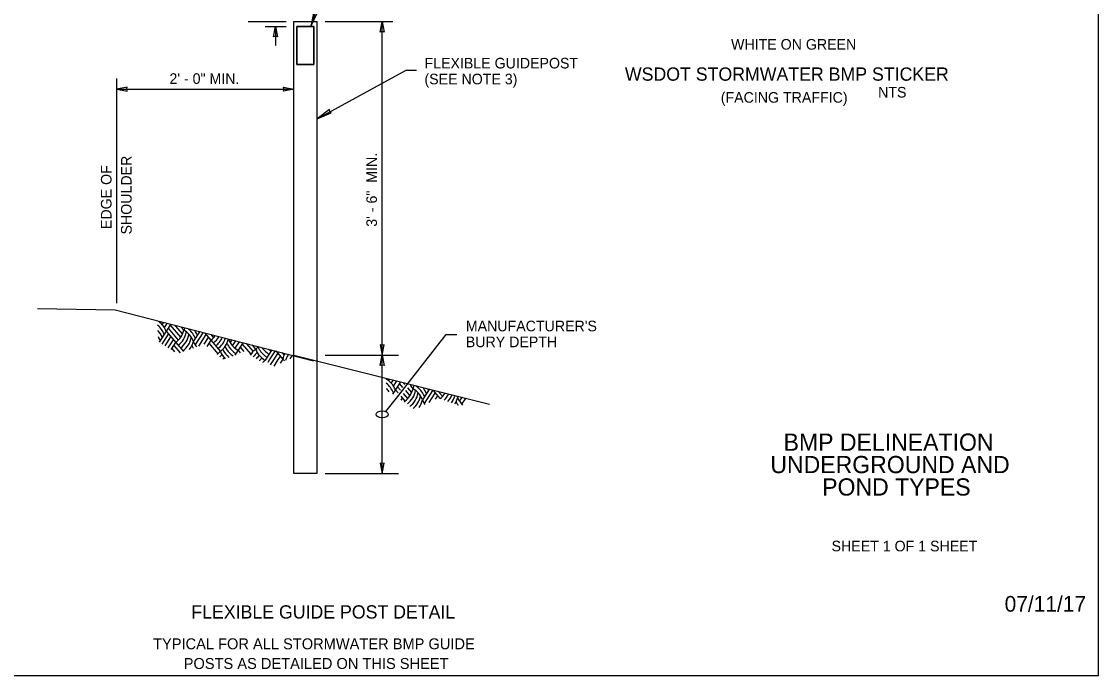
# Model space of a CAD drawing. Extents: x 99862 to 103151, y 100000 to 102076.
# Drawn here: x 101526 to 103151, y 100000 to 100986 of the extents above; entities that cross this region are included whole.
import ezdxf

# ---------------------------------------------------------------- set-up
doc = ezdxf.new("R2010")
doc.units = 0
for name, color, linetype in [('Default', 7, 'Continuous'), ('EV_EC_VegetativeFilterStripNew', 7, 'Continuous'), ('Level 1', 7, 'Continuous'), ('Level 13', 7, 'Continuous'), ('Level 15', 7, 'Continuous'), ('Level 20', 7, 'Continuous'), ('Level 4', 7, 'Continuous'), ('Level 5', 7, 'Continuous'), ('Level 62', 7, 'Continuous'), ('SH_DE_DetailLevel9', 7, 'Continuous')]:
    doc.layers.add(name, color=color, linetype=linetype)

msp = doc.modelspace()

# ---------------------------------------------------------------- linework, layer by layer
at = {"layer": 'Default'}
for p, q in [((101549.7, 100553.4), (101667.1, 100551.1)), ((101936.8, 100482.8), (102017, 100462.7)), ((102017, 100462.7), (102231.7, 100409.1))]:
    msp.add_line(p, q, dxfattribs=at)
at = {"layer": 'EV_EC_VegetativeFilterStripNew'}
msp.add_line((101667.1, 100551.1), (101966.1, 100474.4), dxfattribs=at)
at = {"layer": 'Level 1'}
msp.add_lwpolyline([(99862, 99999.5), (103151, 99999.5), (103151, 102075.5), (99862, 102075.5)], close=True, dxfattribs=at)
at = {"layer": 'Level 13'}
for p, q in [((101733.9, 100532.7), (101734.3, 100533.3)), ((101737.8, 100528.9), (101739.8, 100531.9)), ((101741.2, 100524.4), (101745.2, 100530.5)), ((101750.7, 100529.1), (101744, 100518.9)), ((101750, 100528.2), (101765.7, 100509.8)), ((101744, 100518.9), (101733.3, 100502.5)), ((101737.8, 100499.7), (101747.6, 100514.7)), ((101744, 100518.9), (101758.4, 100502)), ((101747, 100523.5), (101762.3, 100505.6)), ((101757.7, 100527.4), (101768.5, 100514.8)), ((101766.6, 100525.1), (101770.5, 100520.6)), ((101794.3, 100518.1), (101784.9, 100503.7)), ((101787.7, 100498.2), (101799.8, 100516.8)), ((101793, 100496.7), (101804.2, 100513.9)), ((101802.3, 100516.1), (101811.5, 100505.4)), ((101811.2, 100513.9), (101815.4, 100509)), ((101742.3, 100496.9), (101751.2, 100510.5)), ((101746.8, 100494.1), (101754.8, 100506.2)), ((101751.3, 100491.2), (101758.4, 100502)), ((101755.3, 100497.4), (101764.9, 100486.2)), ((101758.4, 100502), (101770.2, 100488.2)), ((101801.2, 100499.4), (101807.9, 100509.7)), ((101811.5, 100505.4), (101805.3, 100496.1)), ((101808.4, 100500.8), (101821.9, 100485)), ((101811.5, 100505.4), (101825.9, 100488.6)), ((101838, 100507.1), (101838, 100507.1)), ((101840.7, 100501.6), (101843.5, 100505.8)), ((101844.1, 100497.1), (101848.9, 100504.4)), ((101848, 100493.3), (101854.4, 100503)), ((101859.8, 100501.7), (101852.4, 100490.3)), ((101855.4, 100494.9), (101861.1, 100488.3)), ((101858.5, 100499.6), (101871.6, 100484.2)), ((101864.7, 100500.4), (101875, 100488.4)), ((101873.7, 100498.2), (101878.9, 100492)), ((101752.3, 100492.8), (101756.3, 100488.1)), ((101852.4, 100490.3), (101847.6, 100483)), ((101852.4, 100490.3), (101855.8, 100486.3)), ((101903.5, 100490.7), (101893.3, 100475.2)), ((101900, 100475.6), (101909.1, 100489.5)), ((101906.6, 100476), (101912.7, 100485.3)), ((101909.3, 100489.2), (101919.9, 100476.9)), ((101913.2, 100476.4), (101916.3, 100481.1)), ((101918.3, 100486.9), (101921.9, 100482.7)), ((101897.7, 100472.1), (101900, 100475.6)), ((101901.6, 100468.4), (101906.6, 100476)), ((101906.7, 100466.4), (101913.2, 100476.4)), ((101919.9, 100476.9), (101916.1, 100471)), ((101919.9, 100476.9), (101922.3, 100474.1)), ((102079.8, 100444.4), (102080.9, 100446)), ((102083.7, 100440.6), (102086.4, 100444.7)), ((102089.9, 100430.6), (102085.5, 100424)), ((102087.1, 100436.1), (102091.8, 100443.3)), ((102097.3, 100441.9), (102089.9, 100430.6)), ((102089.9, 100430.6), (102093.9, 100425.9)), ((102092.9, 100435.2), (102097.5, 100429.9)), ((102095.9, 100439.8), (102100.7, 100434.3)), ((102102.2, 100440.7), (102104, 100438.6)), ((102108.3, 100433.5), (102114.4, 100426.5)), ((102112.1, 100437.4), (102116.4, 100432.3)), ((102141, 100430.9), (102130.8, 100415.4)), ((102098, 100421.1), (102104.3, 100413.7)), ((102098.6, 100414.8), (102100.7, 100417.9)), ((102101.6, 100425.1), (102108.2, 100417.3)), ((102104.3, 100413.7), (102103, 100411.8)), ((102104.9, 100429.4), (102111.6, 100421.5)), ((102133.6, 100409.9), (102146.5, 100429.8)), ((102141, 100411.6), (102150.1, 100425.6)), ((102146.8, 100429.5), (102156.9, 100417.7)), ((102150.4, 100416.3), (102153.7, 100421.3)), ((102155.7, 100427.2), (102161.3, 100420.7)), ((102164.7, 100425), (102164.7, 100424.9)), ((102183.9, 100418.8), (102184.6, 100419.9)), ((102186.6, 100413.3), (102190.1, 100418.6)), ((102190, 100408.8), (102195.5, 100417.2))]:
    msp.add_line(p, q, dxfattribs=at)
for centre, start, end in [((101709.6, 100502), 21.3138, 50.5158), ((101712.6, 100506.6), 21.3138, 53.3766), ((101706.6, 100497.4), 21.3138, 42.1564), ((101737.9, 100528.7), 307.574, 346.0269), ((101741.5, 100524.5), 307.574, 348.6816), ((101745.1, 100520.3), 307.574, 349.9902), ((101799.6, 100516.7), 165.613, 166.0269), ((101803.2, 100512.5), 160.1478, 166.0269), ((101753.6, 100491.5), 21.3138, 59.7667), ((101756.6, 100496.1), 35.002, 51.0452), ((101756.6, 100496.1), 21.3138, 35.0021), ((101759.6, 100500.8), 21.3138, 34.6327), ((101762.7, 100505.4), 21.3138, 22.4807), ((101790.9, 100532.1), 307.574, 323.6606), ((101703.5, 100492.7), 21.3138, 31.8403), ((101748.7, 100516.1), 307.574, 349.4417), ((101752.3, 100511.9), 322.74, 346.0269), ((101813.2, 100511.3), 204.5482, 211.8304), ((101816.3, 100516), 201.3139, 217.591), ((101794.5, 100527.9), 307.574, 329.4442), ((101798.1, 100523.7), 307.574, 335.0599), ((101801.7, 100519.5), 307.574, 340.572), ((101805.3, 100515.3), 307.574, 346.0269), ((101863.3, 100510.1), 205.1047, 224.612), ((101866.3, 100514.7), 204.5482, 215.0023), ((101806.6, 100494.9), 21.3138, 21.3238), ((101869.3, 100519.4), 201.3139, 239.7667), ((101866.3, 100514.7), 215.0022, 239.7667), ((101854.8, 100522.9), 307.574, 310.7344), ((101858.4, 100518.7), 307.574, 317.1654), ((101913.3, 100508.9), 203.9136, 232.6303), ((101846.4, 100461.9), 127.574, 139.497), ((101850, 100457.7), 129.9766, 137.7179), ((101857.2, 100500.8), 201.3138, 224.3945), ((101853.6, 100453.5), 130.7709, 135.9353), ((101860.2, 100505.5), 203.9136, 230.4364), ((101863.3, 100510.1), 224.6119, 236.8532), ((101899.5, 100465.3), 127.574, 148.4574), ((101903.1, 100461.1), 129.9766, 145.5562), ((101910.3, 100504.2), 201.3138, 239.7667), ((101906.7, 100456.9), 130.7709, 142.6477), ((101916.4, 100513.5), 214.6079, 224.612), ((101916.4, 100513.5), 224.6119, 239.7667), ((101913.3, 100508.9), 232.6302, 239.7667), ((101919.4, 100518.1), 231.0063, 239.7667), ((101952.5, 100468.7), 149.8498, 166.0269), ((101956.1, 100464.5), 144.0807, 157.897), ((101959.7, 100460.3), 138.0682, 149.1614), ((101910.3, 100452.7), 139.383, 139.724), ((101910.3, 100452.7), 130.0013, 139.3831), ((101913.9, 100448.5), 127.574, 136.7772), ((101956.1, 100464.5), 157.8969, 161.8589), ((102058.5, 100418.3), 21.3138, 59.7667), ((102055.5, 100413.7), 21.3138, 52.6301), ((102052.4, 100409.1), 32.9159, 44.6118), ((102083.8, 100440.4), 307.574, 346.0269), ((102145.5, 100428.4), 163.5014, 166.0269), ((102149.1, 100424.2), 158.0219, 166.0269), ((102099.5, 100403.2), 21.3138, 59.7667), ((102102.5, 100407.8), 35.002, 56.6803), ((102105.5, 100412.5), 21.3138, 37.946), ((102108.6, 100417.1), 21.3138, 25.1578), ((102087.4, 100436.2), 307.574, 348.6816), ((102091, 100432), 307.574, 349.9902), ((102094.6, 100427.8), 310.7187, 349.4417), ((102098.2, 100423.6), 324.3833, 346.0269), ((102102.5, 100407.8), 21.3138, 35.0021), ((102162.2, 100427.7), 201.3139, 214.8748), ((102136.8, 100443.8), 308.2655, 325.9231), ((102140.4, 100439.6), 313.5377, 331.6331), ((102144, 100435.4), 318.5798, 337.2018), ((102147.6, 100431.2), 323.4546, 342.6888), ((102151.2, 100427), 328.2102, 346.0269), ((102152.5, 100406.6), 21.3138, 23.9592), ((102215.2, 100431.1), 201.3139, 224.7347), ((102212.2, 100426.4), 204.5482, 214.0621)]:
    msp.add_arc(centre, 33.7, start, end, dxfattribs=at)
at = {"layer": 'Level 15'}
for p, q in [((101983.7, 100986.2), (102086, 100986.2)), ((102106, 100912.8), (102122, 100912.8)), ((101669.5, 100561.4), (101669.5, 100900.3)), ((102166.7, 100514), (102182.7, 100514)), ((101983.7, 100482.8), (102094.5, 100482.8)), ((101983.7, 100304.2), (102094.5, 100304.2))]:
    msp.add_line(p, q, dxfattribs=at)
for points in [[(101962.5, 100979.1), (101972.4, 100999.8), (101969.3, 100999.8), (101966.8, 101001.7)], [(102070, 100986.2), (102073.1, 100970.5), (102070, 100971.2), (102067, 100970.5)], [(101669.5, 100884.3), (101685.2, 100881.2), (101684.5, 100884.3), (101685.2, 100887.4)], [(101936.8, 100884.3), (101921.1, 100881.2), (101921.8, 100884.3), (101921.1, 100887.4)], [(101971.9, 100839.7), (101993.2, 100848.5), (101990.8, 100850.5), (101990.2, 100853.7)], [(102070, 100482.8), (102073.1, 100498.5), (102070, 100497.8), (102067, 100498.5)], [(102070, 100482.8), (102073.1, 100467.1), (102070, 100467.8), (102067, 100467.1)], [(102070, 100304.2), (102073.1, 100319.9), (102070, 100319.2), (102067, 100319.9)]]:
    msp.add_lwpolyline(points, close=True, dxfattribs=at)
msp.add_ellipse((102070, 100393.5), major_axis=(-9.21, 0), ratio=0.57735, dxfattribs=at)
at = {"layer": 'Level 4'}
msp.add_lwpolyline([(101941, 100921.7), (101966.7, 100921.7), (101966.7, 100979.1), (101941, 100979.1), (101941, 100921.7)], dxfattribs=at)
at = {"layer": 'Level 5'}
for points in [[(101936.8, 100482.8), (101936.8, 100986.2), (101971.1, 100986.2), (101971.1, 100474.2)], [(101941, 100979.1), (101941, 100921.7), (101966.7, 100921.7), (101966.7, 100979.1), (101953.9, 100979.1), (101941, 100979.1)], [(101971.1, 100474.2), (101971.1, 100304.2), (101936.8, 100304.2), (101936.8, 100482.8)]]:
    msp.add_lwpolyline(points, dxfattribs=at)
msp.add_lwpolyline([(101941, 100979.1), (101966.7, 100979.1), (101966.7, 100921.7), (101941, 100921.7)], close=True, dxfattribs=at)
at = {"layer": 'SH_DE_DetailLevel9'}
for p, q in [((101962.5, 100979.1), (102003, 101101.1)), ((101867.9, 100986.2), (101925.1, 100986.2)), ((102070, 100482.8), (102070, 100986.2)), ((101893.5, 100979.1), (101925.1, 100979.1)), ((101908.8, 100979.1), (101908.8, 100950.4)), ((101971.9, 100839.7), (102106, 100912.8)), ((101669.5, 100884.3), (101936.8, 100884.3)), ((102091.4, 100417.8), (102166.7, 100514)), ((102070, 100304.2), (102070, 100482.8)), ((102075.7, 100397.7), (102091.4, 100417.8))]:
    msp.add_line(p, q, dxfattribs=at)
msp.add_lwpolyline([(101908.8, 100979.1), (101911.9, 100963.3), (101908.8, 100964.1), (101905.7, 100963.3)], close=True, dxfattribs=at)

# ---------------------------------------------------------------- texts
at = {"layer": 'Level 15'}
msp.add_text('07/11/17', height=23.62, dxfattribs=at).set_placement((103009.4, 100095.8))
at = {"layer": 'Level 20'}
for s, height, p in [('WHITE ON GREEN', 16, (102596.5, 100944)), ('FLEXIBLE GUIDEPOST ', 16, (102133.8, 100915.6)), ('2\' - 0" MIN.', 16, (101748.9, 100892.3)), ('(SEE NOTE 3)', 16, (102133.8, 100891.6)), ('WSDOT STORMWATER BMP STICKER', 20, (102436.3, 100897.1)), ('NTS', 16, (102818.4, 100871.7)), ('(FACING TRAFFIC)', 16, (102581, 100863.9)), ("MANUFACTURER'S ", 16, (102196.2, 100518.9)), ('BURY DEPTH', 16, (102196.2, 100494.9)), ('FLEXIBLE GUIDE POST DETAIL', 20, (101781.9, 100085.4)), ('TYPICAL FOR ALL STORMWATER BMP GUIDE ', 16.5, (101724.2, 100039)), ('POSTS AS DETAILED ON THIS SHEET', 16.5, (101770.4, 100009.3))]:
    msp.add_text(s, height=height, dxfattribs=at).set_placement(p)
for s, p in [('SHOULDER', (101691.8, 100665)), ('3\' - 6"  MIN.', (102062, 100676.7)), ('EDGE OF', (101661.5, 100673.2))]:
    msp.add_text(s, height=16, rotation=90, dxfattribs=at).set_placement(p)
at = {"layer": 'Level 62'}
for s, height, p in [('BMP DELINEATION', 26, (102675.8, 100338.6)), ('UNDERGROUND AND ', 26, (102655.8, 100304.8)), ('POND TYPES', 26, (102734, 100271)), ('SHEET 1 OF 1 SHEET', 16, (102748.2, 100186.8))]:
    msp.add_text(s, height=height, dxfattribs=at).set_placement(p)

doc.saveas('drawing.dxf')
